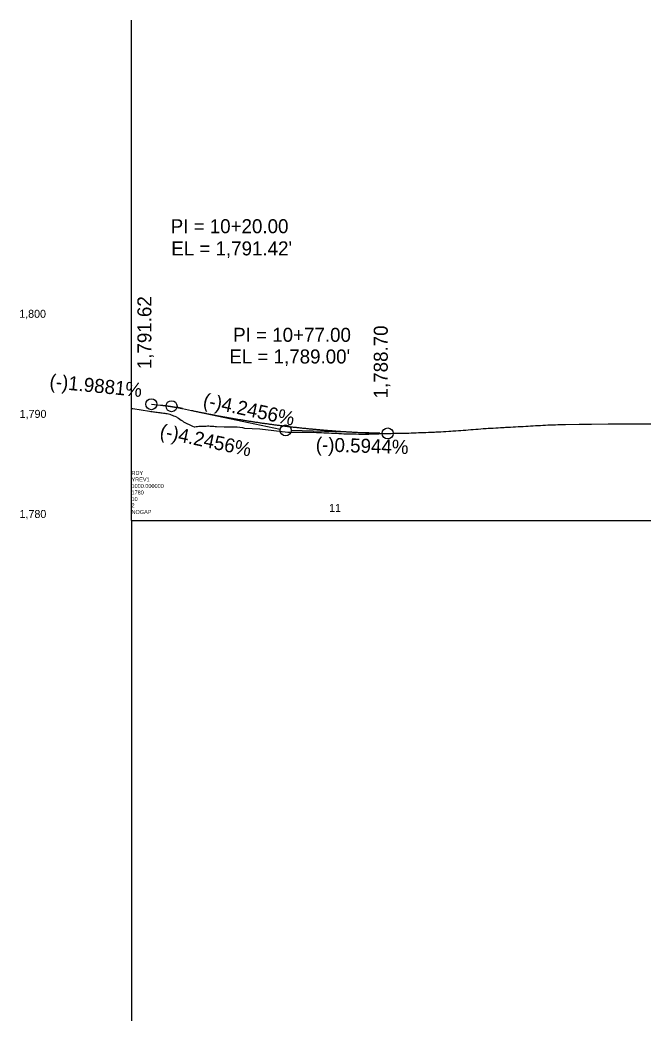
# Model space of a CAD drawing. Extents: x 579695 to 581182, y -53686 to -53165.
# Drawn here: x 579695 to 580011, y -53686 to -53186 of the extents above; entities that cross this region are included whole.
import ezdxf

# ---------------------------------------------------------------- set-up
doc = ezdxf.new("R2010")
doc.units = 0
for name, color, linetype in [('Default', 7, 'Continuous'), ('Exist Profile Cell', 7, 'Continuous'), ('Exist Vertical Profile Ground Line', 7, 'Continuous'), ('Prop Vertical Profile Grade', 7, 'Continuous'), ('Prop Vertical Profile Grade Label', 7, 'Continuous'), ('Prop VPI Label', 7, 'Continuous')]:
    doc.layers.add(name, color=color, linetype=linetype)

msp = doc.modelspace()

# ---------------------------------------------------------------- linework, layer by layer
at = {"layer": 'Exist Profile Cell'}
for q in [(579751.12, -53186.14), (580010.57, -53436.14), (579751.12, -53686.14)]:
    msp.add_line((579751.12, -53436.14), q, dxfattribs=at)
at = {"layer": 'Exist Vertical Profile Ground Line'}
msp.add_lwpolyline([(579751.12, -53380.18), (579751.72, -53380.19), (579760.18, -53381.53), (579760.81, -53381.63), (579761.44, -53381.73), (579762.07, -53381.82), (579762.69, -53381.91), (579763.32, -53382), (579763.95, -53382.09), (579764.58, -53382.17), (579765.21, -53382.25), (579765.84, -53382.33), (579766.47, -53382.41), (579767.1, -53382.48), (579767.73, -53382.55), (579768.35, -53382.62), (579768.98, -53382.68), (579769.61, -53382.8), (579770.24, -53383.05), (579770.87, -53383.3), (579771.5, -53383.55), (579772.13, -53383.79), (579772.76, -53384.04), (579773.59, -53384.35), (579774.01, -53384.65), (579774.64, -53385.09), (579775.27, -53385.52), (579775.9, -53385.94), (579776.53, -53386.37), (579777.16, -53386.86), (579777.79, -53387.25), (579778.42, -53387.52), (579779.04, -53387.79), (579779.67, -53388.07), (579780.3, -53388.37), (579780.93, -53388.67), (579781.56, -53388.97), (579782.4, -53389.34), (579782.82, -53389.3), (579783.45, -53389.24), (579784.08, -53389.17), (579784.82, -53389.08), (579785.33, -53389.07), (579785.96, -53389.05), (579786.59, -53389.03), (579787.22, -53389), (579787.85, -53388.97), (579788.48, -53388.94), (579789.11, -53388.9), (579789.74, -53388.88), (579790.36, -53388.94), (579790.99, -53388.99), (579791.62, -53389.04), (579792.25, -53389.08), (579792.88, -53389.12), (579793.51, -53389.16), (579797.47, -53389.37), (579803.91, -53389.31), (579806.53, -53389.76), (579807.63, -53390.08), (579815.29, -53390.36), (579829.13, -53391.95), (579833.37, -53392.08), (579838.53, -53392.03), (579839.77, -53392.02), (579841.06, -53392.01), (579842.26, -53392.06), (579843.5, -53392.11), (579844.74, -53392.17), (579845.99, -53392.22), (579847.23, -53392.28), (579848.47, -53392.34), (579849.72, -53392.4), (579850.96, -53392.46), (579852.2, -53392.52), (579853.45, -53392.58), (579854.69, -53392.64), (579855.93, -53392.71), (579857.18, -53392.77), (579857.86, -53392.81), (579858.42, -53392.82), (579859.66, -53392.85), (579860.91, -53392.87), (579862.15, -53392.9), (579863.39, -53392.93), (579864.64, -53392.96), (579865.88, -53392.98), (579867.12, -53393.01), (579867.42, -53393.02), (579868.37, -53392.99), (579869.61, -53392.94), (579870.85, -53392.9), (579872.1, -53392.86), (579873.34, -53392.82), (579874.58, -53392.78), (579875.83, -53392.75), (579877.07, -53392.71), (579878.31, -53392.68), (579879.56, -53392.65), (579880.8, -53392.62), (579882.04, -53392.59), (579883.29, -53392.56), (579884.53, -53392.53), (579885.77, -53392.51), (579887.02, -53392.49), (579888.26, -53392.47), (579889.6, -53392.45), (579890.74, -53392.39), (579891.99, -53392.33), (579892.6, -53392.31), (579893.23, -53392.28), (579894.47, -53392.24), (579895.72, -53392.2), (579896.96, -53392.16), (579898.2, -53392.12), (579899.51, -53392.08), (579900.69, -53392.03), (579901.93, -53391.98), (579902.4, -53391.97), (579903.18, -53391.92), (579904.42, -53391.84), (579905.66, -53391.77), (579906.91, -53391.69), (579908.15, -53391.62), (579909.62, -53391.53), (579910.64, -53391.48), (579911.58, -53391.43), (579911.88, -53391.41), (579913.12, -53391.31), (579914.37, -53391.22), (579915.61, -53391.13), (579916.85, -53391.04), (579918.1, -53390.94), (579919.34, -53390.84), (579920.58, -53390.74), (579921.83, -53390.64), (579923.07, -53390.54), (579924.31, -53390.44), (579925.57, -53390.35), (579926.8, -53390.24), (579928.25, -53390.13), (579929.29, -53390.07), (579930.53, -53390.01), (579931.77, -53389.94), (579933.02, -53389.87), (579934.26, -53389.81), (579935.5, -53389.74), (579936.07, -53389.71), (579936.75, -53389.66), (579937.31, -53389.62), (579937.99, -53389.59), (579939.23, -53389.52), (579940.48, -53389.45), (579941.72, -53389.39), (579942.96, -53389.32), (579944.21, -53389.25), (579945.45, -53389.19), (579946.69, -53389.12), (579948.1, -53389.05), (579949.18, -53388.98), (579950.42, -53388.9), (579950.91, -53388.87), (579951.66, -53388.83), (579952.91, -53388.76), (579954.15, -53388.69), (579955.39, -53388.63), (579956.64, -53388.56), (579957.88, -53388.49), (579959.12, -53388.43), (579959.6, -53388.4), (579960.37, -53388.38), (579961.61, -53388.34), (579962.14, -53388.33), (579962.85, -53388.3), (579964.1, -53388.25), (579965.34, -53388.2), (579966.88, -53388.13), (579967.83, -53388.13), (579974.72, -53388.1), (579980.9, -53387.97), (579989.19, -53387.93), (580000.49, -53387.87), (580009.83, -53387.85), (580010.57, -53387.85)], dxfattribs=at)
at = {"layer": 'Prop Vertical Profile Grade'}
for p, q in [((579761.06, -53378.04), (579765.6, -53378.49)), ((579776.64, -53380.21), (579781.12, -53381.16)), ((579875.12, -53392.54), (579879.1, -53392.66))]:
    msp.add_line(p, q, dxfattribs=at)
for points in [[(579765.6, -53378.49), (579765.82, -53378.51), (579766.04, -53378.54), (579766.27, -53378.56), (579766.49, -53378.58), (579766.71, -53378.61), (579766.93, -53378.63), (579767.15, -53378.66), (579767.37, -53378.68), (579767.59, -53378.71), (579767.81, -53378.74), (579768.03, -53378.76), (579768.25, -53378.79), (579768.47, -53378.82), (579768.69, -53378.85), (579768.91, -53378.88), (579769.14, -53378.91), (579769.36, -53378.94), (579769.58, -53378.97), (579769.8, -53379), (579770.02, -53379.03), (579770.24, -53379.06), (579770.46, -53379.1), (579770.68, -53379.13), (579770.9, -53379.16), (579771.12, -53379.2), (579771.34, -53379.23), (579771.56, -53379.27), (579771.78, -53379.3), (579772.01, -53379.34), (579772.23, -53379.37), (579772.45, -53379.41), (579772.67, -53379.45), (579772.89, -53379.49), (579773.11, -53379.53), (579773.33, -53379.57), (579773.55, -53379.61), (579773.77, -53379.65), (579773.99, -53379.69), (579774.21, -53379.73), (579774.43, -53379.77), (579774.65, -53379.81), (579774.88, -53379.85), (579775.1, -53379.9), (579775.32, -53379.94), (579775.54, -53379.98), (579775.76, -53380.03), (579775.98, -53380.07), (579776.2, -53380.12), (579776.42, -53380.17), (579776.64, -53380.21)], [(579781.12, -53381.16), (579783, -53381.56), (579784.88, -53381.95), (579786.76, -53382.33), (579788.64, -53382.7), (579790.52, -53383.07), (579792.4, -53383.43), (579794.28, -53383.79), (579796.16, -53384.14), (579798.04, -53384.48), (579799.92, -53384.81), (579801.8, -53385.14), (579803.68, -53385.46), (579805.56, -53385.77), (579807.44, -53386.08), (579809.32, -53386.38), (579811.2, -53386.67), (579813.08, -53386.96), (579814.96, -53387.24), (579816.84, -53387.51), (579818.72, -53387.77), (579820.6, -53388.03), (579822.48, -53388.28), (579824.36, -53388.53), (579826.24, -53388.76), (579828.12, -53389), (579830, -53389.22), (579831.88, -53389.44), (579833.76, -53389.65), (579835.64, -53389.85), (579837.52, -53390.05), (579839.4, -53390.24), (579841.28, -53390.42), (579843.16, -53390.6), (579845.04, -53390.76), (579846.92, -53390.93), (579848.8, -53391.08), (579850.68, -53391.23), (579852.56, -53391.37), (579854.44, -53391.51), (579856.32, -53391.64), (579858.2, -53391.76), (579860.08, -53391.87), (579861.96, -53391.98), (579863.84, -53392.08), (579865.72, -53392.17), (579867.6, -53392.26), (579869.48, -53392.34), (579871.36, -53392.41), (579873.24, -53392.48), (579875.12, -53392.54)]]:
    msp.add_spline(points, degree=3, dxfattribs=at)
at = {"layer": 'Prop VPI Label'}
for p, q in [((579765.6, -53378.49), (579768.39, -53378.77)), ((579776.64, -53380.21), (579773.81, -53379.61)), ((579781.12, -53381.16), (579825.43, -53390.57)), ((579875.12, -53392.54), (579830.87, -53391.22))]:
    msp.add_line(p, q, dxfattribs=at)
for centre in [(579761.06, -53378.04), (579771.12, -53379.04), (579828.12, -53391.14), (579879.1, -53392.66)]:
    msp.add_circle(centre, 2.75, dxfattribs=at)

# ---------------------------------------------------------------- texts
at = {"layer": 'Default'}
for s, p in [('1,800', (579695.04, -53334.89)), ('1,790', (579695.26, -53384.89)), ('11', (579849.8, -53431.89)), ('1,780', (579695.2, -53434.89))]:
    msp.add_text(s, height=4, dxfattribs=at).set_placement(p)
at = {"layer": 'Exist Profile Cell'}
for s, p in [('YREV1', (579751.12, -53416.64)), ('RDY', (579751.12, -53413.39)), ('1000.000000', (579751.12, -53419.89)), ('1780', (579751.12, -53423.14)), ('10', (579751.12, -53426.39)), ('2', (579751.12, -53429.64)), ('NOGAP', (579751.12, -53432.89))]:
    msp.add_text(s, height=2, dxfattribs=at).set_placement(p)
at = {"layer": 'Prop Vertical Profile Grade Label'}
for s, rotation, p in [('(-)1.9881%', 354.3232, (579709.95, -53369.95)), ('(-)4.2456%', 348.0151, (579786.45, -53379.23)), ('(-)4.2456%', 348.0151, (579764.85, -53394.65)), ('(-)0.5944%', 358.2978, (579843.08, -53401.59))]:
    msp.add_text(s, height=7, rotation=rotation, dxfattribs=at).set_placement(p)
at = {"layer": 'Prop VPI Label'}
for s, p in [('PI = 10+20.00', (579770.7, -53292.63)), ("EL = 1,791.42'", (579770.98, -53303.72)), ('PI = 10+77.00', (579801.9, -53346.89)), ("EL = 1,789.00'", (579799.98, -53357.71))]:
    msp.add_text(s, height=7, dxfattribs=at).set_placement(p)
for s, p in [('1,791.62', (579761.06, -53360.54)), ('1,788.70', (579879.1, -53375.16))]:
    msp.add_text(s, height=7, rotation=90, dxfattribs=at).set_placement(p)

doc.saveas('drawing.dxf')
